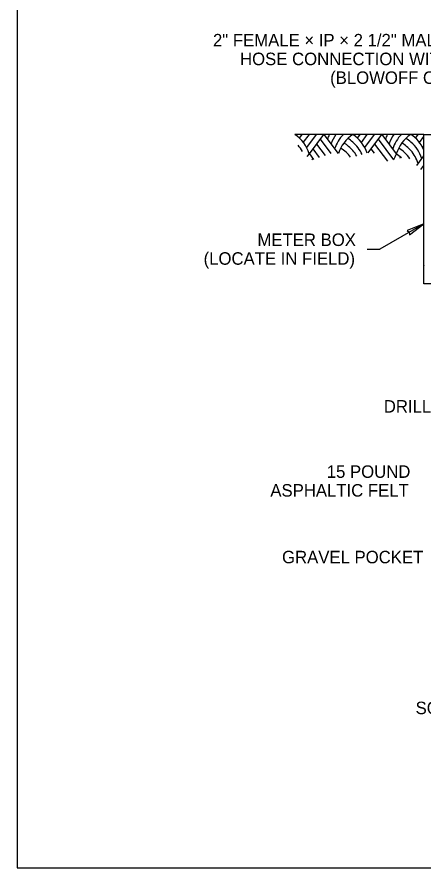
# Model space of a CAD drawing. Extents: x 99862 to 103151, y 99999 to 102075.
# Drawn here: x 99862 to 100383, y 99999 to 101089 of the extents above; entities that cross this region are included whole.
import ezdxf

# ---------------------------------------------------------------- set-up
doc = ezdxf.new("R2010")
doc.units = 0
for name, color, linetype in [('Level 1', 7, 'Continuous'), ('Level 10', 7, 'Continuous'), ('Level 15', 7, 'Continuous'), ('Level 17', 7, 'Continuous'), ('Level 20', 7, 'Continuous'), ('Level 60', 7, 'Continuous')]:
    doc.layers.add(name, color=color, linetype=linetype)

msp = doc.modelspace()

# ---------------------------------------------------------------- linework, layer by layer
at = {"layer": 'Level 1'}
msp.add_line((100382.4, 100772), (100382.5, 100770.9), dxfattribs=at)
msp.add_lwpolyline([(99862, 99999.5), (103151, 99999.5), (103151, 102075.5), (99862, 102075.5)], close=True, dxfattribs=at)
at = {"layer": 'Level 10'}
msp.add_line((100382.5, 100916.9), (100382.5, 100916.9), dxfattribs=at)
at = {"layer": 'Level 15'}
for p, q in [((100382.5, 100938.5), (100217.5, 100938.5)), ((100382.5, 100824.2), (100326.2, 100791.7)), ((100310.2, 100791.7), (100326.2, 100791.7))]:
    msp.add_line(p, q, dxfattribs=at)
msp.add_lwpolyline([(100382.5, 100824.2), (100361.3, 100815.4), (100363.7, 100813.4), (100364.3, 100810.2)], close=True, dxfattribs=at)
at = {"layer": 'Level 17'}
for p, q in [((100382.5, 100938.5), (100394.7, 100938.5)), ((100382.5, 100747.2), (100382.5, 100938.5)), ((100406.2, 100747.2), (100382.5, 100747.2))]:
    msp.add_line(p, q, dxfattribs=at)
at = {"layer": 'Level 20'}
for p, q in [((100223.3, 100933.8), (100226.8, 100938.5)), ((100228.4, 100928.3), (100236.1, 100938.5)), ((100232.7, 100921.6), (100245.4, 100938.5)), ((100236.1, 100913.7), (100254.6, 100938.5)), ((100254.6, 100938.5), (100272.8, 100914.3)), ((100297.6, 100933.8), (100301, 100938.5)), ((100302.7, 100928.3), (100310.3, 100938.5)), ((100307, 100921.6), (100319.6, 100938.5)), ((100311.2, 100914.9), (100328.9, 100938.5)), ((100328.9, 100938.5), (100347.4, 100913.7)), ((100371.8, 100933.8), (100375.3, 100938.5)), ((100376.9, 100928.3), (100382.6, 100935.8)), ((100245.4, 100926.1), (100256.2, 100911.7)), ((100250, 100932.3), (100263.6, 100914.2)), ((100319.6, 100926.1), (100336, 100904.3)), ((100324.2, 100932.3), (100343.9, 100906.1)), ((100233.5, 100910.3), (100236.1, 100913.7)), ((100236.1, 100913.7), (100241.4, 100906.6)), ((100240.7, 100919.9), (100248.8, 100909.1)), ((100315, 100919.9), (100318.9, 100914.6)), ((100381.2, 100921.6), (100382.5, 100923.4)), ((100239.6, 100906), (100240.7, 100907.5)), ((100373.5, 100898.9), (100382.5, 100911)), ((100378.8, 100893.7), (100382.5, 100898.6))]:
    msp.add_line(p, q, dxfattribs=at)
for centre, start, end in [((100191.3, 100899.5), 56.0953, 56.0963), ((100191.3, 100899.5), 17.6434, 56.0953), ((100304, 100918), 154.2266, 162.3566), ((100308.7, 100911.9), 145.491, 162.3566), ((100313.3, 100905.7), 135.7127, 162.3566), ((100318, 100899.5), 123.9036, 161.8571), ((100265.6, 100899.5), 18.6768, 56.0963), ((100378.3, 100918), 154.2266, 162.3566), ((100382.9, 100911.9), 145.491, 162.3566), ((100387.6, 100905.7), 135.7127, 162.3566), ((100392.2, 100899.5), 123.9036, 162.3566), ((100339.8, 100899.5), 24.5181, 56.0963), ((100186.7, 100893.3), 29.6405, 41.9997), ((100256.3, 100887.1), 40.9413, 59.3021), ((100260.9, 100893.3), 48.9597, 58.5465), ((100260.9, 100893.3), 24.3212, 48.9597), ((100330.5, 100887.1), 40.9413, 59.3021), ((100335.2, 100893.3), 48.9597, 58.5465), ((100335.2, 100893.3), 17.6434, 48.9597), ((100251.6, 100880.9), 37.5224, 58.4874), ((100256.3, 100887.1), 30.0427, 40.9414), ((100302.7, 100928), 332.4324, 342.3566), ((100321.2, 100874.7), 45.8578, 56.0964), ((100325.9, 100880.9), 34.4073, 58.4874), ((100330.5, 100887.1), 17.6434, 40.9414), ((100307.3, 100921.8), 343.0137, 345.0113)]:
    msp.add_arc(centre, 47, start, end, dxfattribs=at)
at = {"layer": 'Level 60'}
msp.add_line((99862, 99999.5), (99862, 99999.5), dxfattribs=at)

# ---------------------------------------------------------------- texts
at = {"layer": 'Level 20'}
for s, p in [('2" FEMALE × IP × 2 1/2" MALE NST', (100112.8, 101051.2)), ('HOSE CONNECTION WITH CAP', (100147.4, 101027.2)), ('(BLOWOFF OUTLET)', (100262.7, 101003.2)), ('METER BOX', (100169.7, 100795.7)), ('(LOCATE IN FIELD)', (100100.8, 100771.7)), ('DRILL 1/8" HOLE', (100331.4, 100582.4)), ('15 POUND', (100258.4, 100498.9)), ('ASPHALTIC FELT', (100186.2, 100474.9)), ('GRAVEL POCKET', (100201.2, 100389.5)), ('SOLID CONCRETE BEARING', (100372.1, 100196.4))]:
    msp.add_text(s, height=16, dxfattribs=at).set_placement(p)

doc.saveas('drawing.dxf')
